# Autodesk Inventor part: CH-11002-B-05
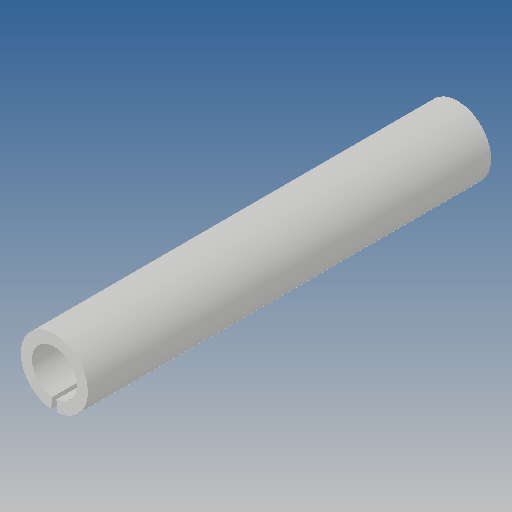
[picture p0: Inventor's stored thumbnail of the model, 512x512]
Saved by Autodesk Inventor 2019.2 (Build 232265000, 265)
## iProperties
Created: 2012-09
Part Number: CH-11002-B-05
Material: Ogólny
Document SubType Name: Modeling
Designer: CADENGINEERING4
Density: 1 g/cm^3
Appearance: Domyślna
Author: CADENGINEERING4
Revision Number: ÈÎºÎ
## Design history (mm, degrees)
feature "À­Éì1"
node "Bryła1"
